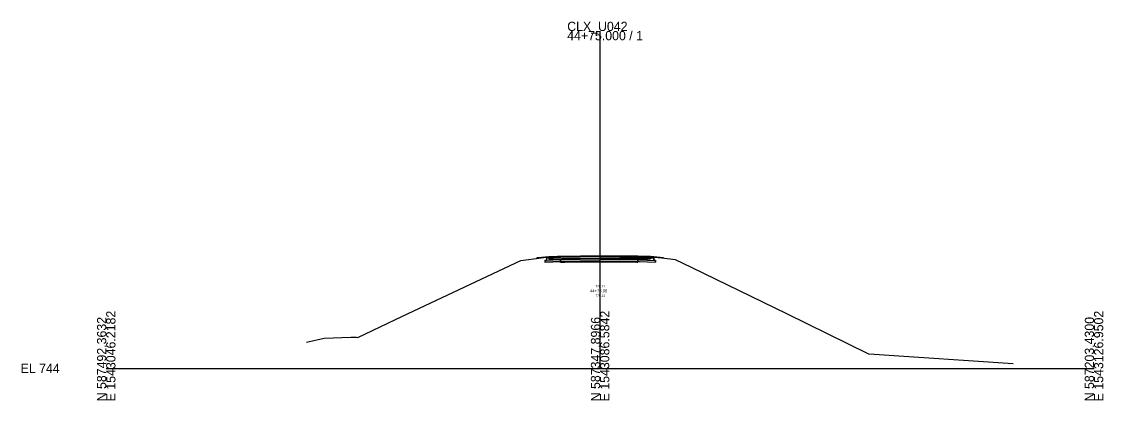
# Model space of a CAD drawing. Extents: x -26 to 1603, y -10 to 5557.
# Drawn here: x -25.7 to 302.8, y 1490.3 to 1605.2 of the extents above; entities that cross this region are included whole.
import ezdxf

# ---------------------------------------------------------------- set-up
doc = ezdxf.new("R2010")
doc.units = 0
for name, color, linetype in [('GK_Cells', 7, 'Continuous'), ('XS_P_Annotation', 7, 'Continuous'), ('XS_P_Earthwork_Shapes', 7, 'Continuous'), ('XS_P_Finished_Grade', 7, 'Continuous'), ('XS_P_Pavt_Layers', 7, 'Continuous'), ('XS_P_Pavt_Surface', 7, 'Continuous'), ('XS_P_Shoulder_Layers', 7, 'Continuous'), ('XS_P_Shoulder_Surface', 7, 'Continuous'), ('XS_P_Subgrade', 7, 'Continuous'), ('XS_X_Ground_Line', 7, 'Continuous'), ('XS_X_Pavt', 7, 'Continuous')]:
    doc.layers.add(name, color=color, linetype=linetype)

msp = doc.modelspace()

# ---------------------------------------------------------------- linework, layer by layer
at = {"layer": 'GK_Cells'}
for p, q in [((150, 1500), (150, 1602.33)), ((0, 1500), (150, 1500)), ((150, 1500), (300, 1500))]:
    msp.add_line(p, q, dxfattribs=at)
at = {"layer": 'XS_P_Earthwork_Shapes'}
for points in [[(131, 1533.5), (130.72, 1533.37), (132.11, 1533.54), (133.28, 1533.69)], [(131, 1533.5), (130.72, 1533.37), (132.11, 1533.54), (133.28, 1533.69)], [(131, 1533.5), (130.72, 1533.37), (132.11, 1533.54), (133.28, 1533.69)], [(131, 1533.5), (130.72, 1533.37), (132.11, 1533.54), (133.28, 1533.69)], [(133.67, 1533.47), (133.67, 1532.72), (133.17, 1532.7), (133.17, 1532.2), (137.98, 1532.39), (137.98, 1533.17), (137.07, 1533.15), (134.57, 1533.1), (134.57, 1533.85), (134.42, 1533.84), (133.28, 1533.69), (134, 1533.75), (134, 1533.48)], [(133.67, 1533.47), (133.67, 1532.72), (133.17, 1532.7), (133.17, 1532.2), (137.98, 1532.39), (137.98, 1533.17), (137.07, 1533.15), (134.57, 1533.1), (134.57, 1533.85), (134.42, 1533.84), (133.28, 1533.69), (134, 1533.75), (134, 1533.48)], [(133.67, 1533.47), (133.67, 1532.72), (133.17, 1532.7), (133.17, 1532.2), (137.98, 1532.39), (137.98, 1533.17), (137.07, 1533.15), (134.57, 1533.1), (134.57, 1533.85), (134.42, 1533.84), (133.28, 1533.69), (134, 1533.75), (134, 1533.48)], [(133.17, 1532.7), (133.17, 1532.2), (137.98, 1532.39), (137.98, 1533.17), (137.07, 1533.15), (134.57, 1533.1), (134.57, 1533.85), (134.42, 1533.84), (133.28, 1533.69), (134, 1533.75), (134, 1533.48), (133.67, 1533.47), (133.67, 1532.72)], [(134.57, 1533.85), (137.07, 1533.9), (138.34, 1533.93), (139.3, 1533.94), (149.83, 1534.11), (161.13, 1534), (161.44, 1534), (165.28, 1533.95), (165.35, 1533.94), (165.35, 1533.19), (165.28, 1533.2), (161.47, 1533.25), (161.44, 1533.25), (161.13, 1533.25), (149.83, 1533.36), (139.3, 1533.19), (138.34, 1533.18), (137.98, 1533.17), (137.07, 1533.15), (134.57, 1533.1)], [(161.44, 1533.25), (161.47, 1533.25), (165.28, 1533.2), (165.35, 1533.19), (165.35, 1533.94), (165.28, 1533.95), (161.44, 1534), (161.13, 1534), (149.83, 1534.11), (139.3, 1533.94), (138.34, 1533.93), (137.07, 1533.9), (134.57, 1533.85), (134.57, 1533.1), (137.07, 1533.15), (137.98, 1533.17), (138.34, 1533.18), (139.3, 1533.19), (149.83, 1533.36), (161.13, 1533.25)], [(161.44, 1534), (165.28, 1533.95), (165.35, 1533.94), (165.35, 1533.19), (165.28, 1533.2), (161.47, 1533.25), (161.44, 1533.25), (161.13, 1533.25), (149.83, 1533.36), (139.3, 1533.19), (138.34, 1533.18), (137.98, 1533.17), (137.07, 1533.15), (134.57, 1533.1), (134.57, 1533.85), (137.07, 1533.9), (138.34, 1533.93), (139.3, 1533.94), (149.83, 1534.11), (161.13, 1534)], [(161.44, 1534), (165.28, 1533.95), (165.35, 1533.94), (165.35, 1533.19), (165.28, 1533.2), (161.47, 1533.25), (161.44, 1533.25), (161.13, 1533.25), (149.83, 1533.36), (139.3, 1533.19), (138.34, 1533.18), (137.98, 1533.17), (137.07, 1533.15), (134.57, 1533.1), (134.57, 1533.85), (137.07, 1533.9), (138.34, 1533.93), (139.3, 1533.94), (149.83, 1534.11), (161.13, 1534)], [(138.04, 1532.39), (150, 1532.59), (161.47, 1532.4), (161.47, 1533.25), (161.44, 1533.25), (161.13, 1533.25), (149.83, 1533.36), (139.3, 1533.19), (138.34, 1533.18), (137.98, 1533.17), (137.98, 1532.39)], [(138.04, 1532.39), (150, 1532.59), (161.47, 1532.4), (161.47, 1533.25), (161.44, 1533.25), (161.13, 1533.25), (149.83, 1533.36), (139.3, 1533.19), (138.34, 1533.18), (137.98, 1533.17), (137.98, 1532.39)], [(138.04, 1532.39), (150, 1532.59), (161.47, 1532.4), (161.47, 1533.25), (161.44, 1533.25), (161.13, 1533.25), (149.83, 1533.36), (139.3, 1533.19), (138.34, 1533.18), (137.98, 1533.17), (137.98, 1532.39)], [(138.04, 1532.39), (150, 1532.59), (161.47, 1532.4), (161.47, 1533.25), (161.44, 1533.25), (161.13, 1533.25), (149.83, 1533.36), (139.3, 1533.19), (138.34, 1533.18), (137.98, 1533.17), (137.98, 1532.39)], [(166, 1533.48), (166, 1533.75), (169.22, 1533.49), (165.35, 1533.94), (165.35, 1533.19), (165.28, 1533.2), (161.47, 1533.25), (161.47, 1532.4), (161.96, 1532.39), (166.83, 1532.2), (166.83, 1532.7), (166.33, 1532.72), (166.33, 1533.47)], [(161.96, 1532.39), (166.83, 1532.2), (166.83, 1532.7), (166.33, 1532.72), (166.33, 1533.47), (166, 1533.48), (166, 1533.75), (169.22, 1533.49), (165.35, 1533.94), (165.35, 1533.19), (165.28, 1533.2), (161.47, 1533.25), (161.47, 1532.4)], [(161.96, 1532.39), (166.83, 1532.2), (166.83, 1532.7), (166.33, 1532.72), (166.33, 1533.47), (166, 1533.48), (166, 1533.75), (169.22, 1533.49), (165.35, 1533.94), (165.35, 1533.19), (165.28, 1533.2), (161.47, 1533.25), (161.47, 1532.4)], [(161.96, 1532.39), (166.83, 1532.2), (166.83, 1532.7), (166.33, 1532.72), (166.33, 1533.47), (166, 1533.48), (166, 1533.75), (169.22, 1533.49), (165.35, 1533.94), (165.35, 1533.19), (165.28, 1533.2), (161.47, 1533.25), (161.47, 1532.4)]]:
    msp.add_lwpolyline(points, close=True, dxfattribs=at)
at = {"layer": 'XS_P_Finished_Grade'}
for p, q in [((131, 1533.5), (130.72, 1533.37)), ((134, 1533.75), (131, 1533.5)), ((166, 1533.75), (169.22, 1533.49))]:
    msp.add_line(p, q, dxfattribs=at)
at = {"layer": 'XS_P_Pavt_Layers'}
for p, q in [((133.17, 1532.7), (133.17, 1532.2)), ((133.67, 1533.47), (133.67, 1532.72)), ((134, 1533.75), (134, 1533.48)), ((150, 1533.98), (138, 1533.79)), ((150, 1533.84), (138, 1533.64)), ((150.02, 1533.09), (138.02, 1532.89)), ((150.02, 1532.59), (138.02, 1532.39)), ((149.98, 1533.09), (161.98, 1532.89)), ((149.98, 1532.59), (161.98, 1532.39)), ((150, 1533.98), (162, 1533.79)), ((150, 1533.84), (162, 1533.64)), ((166, 1533.75), (166, 1533.48)), ((166.33, 1533.47), (166.33, 1532.72)), ((166.83, 1532.7), (166.83, 1532.2))]:
    msp.add_line(p, q, dxfattribs=at)
at = {"layer": 'XS_P_Pavt_Surface'}
for q in [(138, 1533.91), (162, 1533.91)]:
    msp.add_line((150, 1534.11), q, dxfattribs=at)
at = {"layer": 'XS_P_Shoulder_Layers'}
for p, q in [((138.04, 1532.89), (133.17, 1532.7)), ((138.06, 1532.4), (133.17, 1532.2)), ((138.01, 1533.64), (133.67, 1533.47)), ((138, 1533.79), (134, 1533.63)), ((161.94, 1532.4), (166.83, 1532.2)), ((161.96, 1532.89), (166.83, 1532.7)), ((161.99, 1533.64), (166.33, 1533.47)), ((162, 1533.79), (166, 1533.63))]:
    msp.add_line(p, q, dxfattribs=at)
at = {"layer": 'XS_P_Shoulder_Surface'}
for p, q in [((138, 1533.91), (134, 1533.75)), ((162, 1533.91), (166, 1533.75))]:
    msp.add_line(p, q, dxfattribs=at)
at = {"layer": 'XS_P_Subgrade'}
msp.add_lwpolyline([(134, 1533.75), (134, 1533.48), (133.67, 1533.47), (133.67, 1532.72), (133.17, 1532.7), (133.17, 1532.2), (138.04, 1532.39), (150, 1532.59), (161.96, 1532.39), (166.83, 1532.2), (166.83, 1532.7), (166.33, 1532.72), (166.33, 1533.47), (166, 1533.48), (166, 1533.75)], dxfattribs=at)
at = {"layer": 'XS_X_Ground_Line'}
msp.add_lwpolyline([(60.79, 1507.93), (66.2, 1509.18), (74.29, 1509.51), (76.01, 1509.43), (76.43, 1509.4), (89.93, 1515.82), (125.89, 1532.74), (132.11, 1533.54), (134.42, 1533.84), (137.07, 1533.9), (138.34, 1533.93), (139.3, 1533.94), (149.83, 1534.11), (161.13, 1534), (161.44, 1534), (165.28, 1533.95), (172.09, 1533.15), (172.79, 1533.07), (175.15, 1531.92), (177.87, 1530.6), (206.6, 1516.61), (231.53, 1504.45), (233.26, 1504.32), (275.45, 1501.48)], dxfattribs=at)
at = {"layer": 'XS_X_Pavt'}
for p, q in [((134.57, 1533.85), (134.57, 1533.1)), ((134.57, 1533.1), (137.07, 1533.15)), ((137.07, 1533.15), (137.98, 1533.17)), ((137.98, 1533.17), (138.34, 1533.18)), ((137.98, 1533.17), (137.98, 1532.17)), ((137.98, 1532.17), (138.34, 1532.18)), ((138.34, 1533.18), (139.3, 1533.19)), ((138.34, 1532.18), (139.3, 1532.19)), ((139.3, 1533.19), (149.83, 1533.36)), ((139.3, 1532.19), (149.83, 1532.36)), ((149.83, 1533.36), (161.13, 1533.25)), ((149.83, 1532.36), (161.13, 1532.25)), ((161.13, 1533.25), (161.44, 1533.25)), ((161.13, 1532.25), (161.44, 1532.25)), ((161.44, 1533.25), (161.47, 1533.25)), ((161.44, 1532.25), (161.47, 1532.25)), ((161.47, 1533.25), (165.28, 1533.2)), ((161.47, 1533.25), (161.47, 1532.25)), ((165.28, 1533.2), (165.35, 1533.19)), ((165.35, 1533.94), (165.35, 1533.19))]:
    msp.add_line(p, q, dxfattribs=at)

# ---------------------------------------------------------------- texts
at = {"layer": 'GK_Cells'}
for s, p in [('CLX_U042', (140, 1602.33)), ('44+75.000 / 1', (140, 1599.53)), ('EL 744', (-26, 1498.6))]:
    msp.add_text(s, height=2.8, dxfattribs=at).set_placement(p)
for s, p in [('N 587492.3632', (0, 1490)), ('E 1543046.2182', (2.8, 1490)), ('N 587347.8966', (150, 1490)), ('E 1543086.5842', (152.8, 1490)), ('N 587203.4300', (300, 1490)), ('E 1543126.9502', (302.8, 1490))]:
    msp.add_text(s, height=2.8, rotation=90, dxfattribs=at).set_placement(p)
at = {"layer": 'XS_P_Annotation'}
for s, height, p in [('778.11', 0.7, (148.56, 1524.55)), ('44+75.00', 0.9, (146.94, 1523.05)), ('778.11', 0.7, (148.56, 1521.75))]:
    msp.add_text(s, height=height, dxfattribs=at).set_placement(p)

doc.saveas('drawing.dxf')
